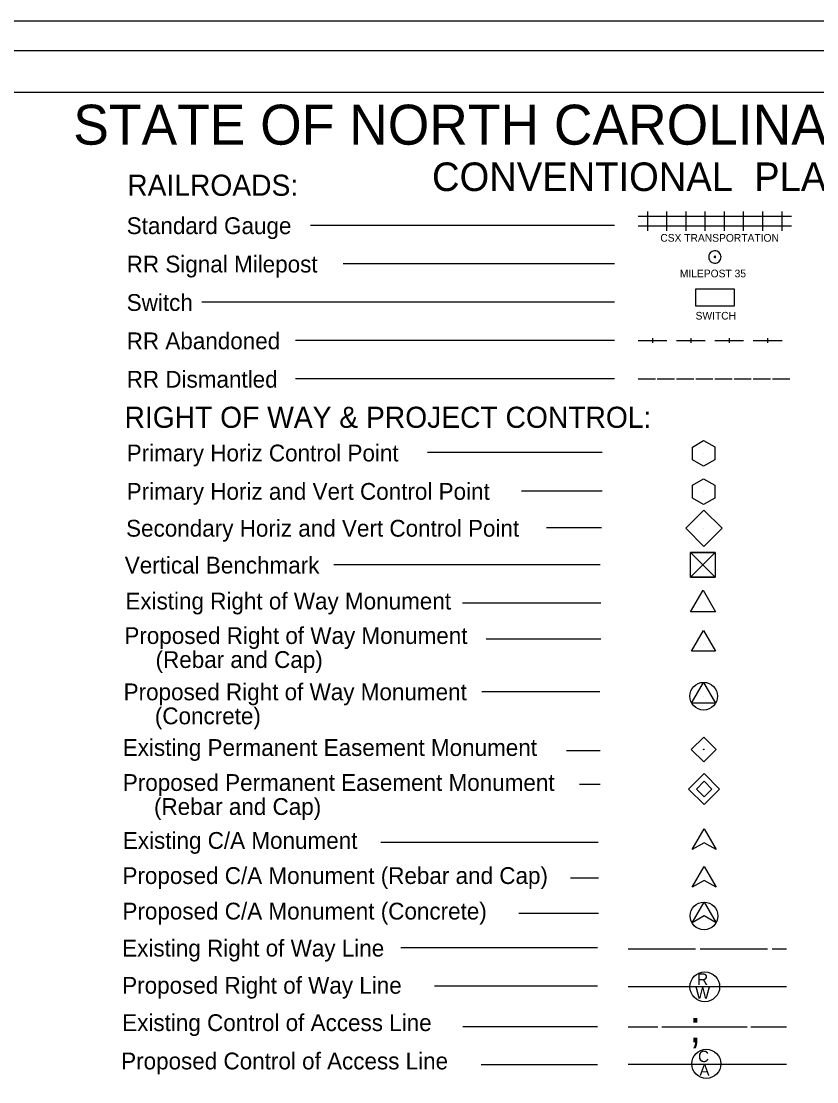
# Model space of a CAD drawing. Extents: x 811508 to 813252, y 647626 to 648754.
# Drawn here: x 811937 to 812366, y 648182 to 648754 of the extents above; entities that cross this region are included whole.
import ezdxf

# ---------------------------------------------------------------- set-up
doc = ezdxf.new("R2010")
doc.units = 0
for name, color, linetype in [('P_RDY_ROW_Permanent_Easement', 7, 'Continuous'), ('Sheet Cutting Line CELL', 7, 'Continuous'), ('Sheet Plot Border Inside CELL', 7, 'Continuous'), ('Sheet Plot Border Outside CELL', 7, 'Continuous'), ('Sheet_Plan', 7, 'Continuous'), ('Sheet_Symbology', 7, 'Continuous'), ('z - Construction', 7, 'Continuous')]:
    doc.layers.add(name, color=color, linetype=linetype)

msp = doc.modelspace()

# ---------------------------------------------------------------- linework, layer by layer
at = {"layer": 'P_RDY_ROW_Permanent_Easement'}
msp.add_line((812305.68, 648339.99), (812305.68, 648339.99), dxfattribs=at)
for points in [[(812305.68, 648348.32), (812314.01, 648339.99), (812305.68, 648331.66), (812297.34, 648339.99)], [(812305.68, 648344.16), (812309.85, 648339.99), (812305.68, 648335.82), (812301.51, 648339.99)]]:
    msp.add_lwpolyline(points, close=True, dxfattribs=at)
at = {"layer": 'Sheet Cutting Line CELL'}
msp.add_line((813217.6, 648737.99), (811533.6, 648737.99), dxfattribs=at)
at = {"layer": 'Sheet Plot Border Inside CELL'}
msp.add_lwpolyline([(811546.6, 647660.44), (813213.1, 647660.44), (813213.1, 648715.54), (811546.6, 648715.54)], close=True, dxfattribs=at)
at = {"layer": 'Sheet Plot Border Outside CELL'}
msp.add_lwpolyline([(811533.6, 647637.99), (813217.6, 647637.99), (813217.6, 648737.99), (811533.6, 648737.99)], close=True, dxfattribs=at)
at = {"layer": 'Sheet_Plan'}
msp.add_line((813213.53, 648715.54), (811546.6, 648715.54), dxfattribs=at)
at = {"layer": 'Sheet_Symbology'}
for p, q in [((812270.08, 648648.82), (812280.43, 648648.82)), ((812275.25, 648641.06), (812275.25, 648651.41)), ((812280.43, 648648.82), (812290.78, 648648.82)), ((812285.6, 648641.06), (812285.6, 648651.41)), ((812290.78, 648648.82), (812301.13, 648648.82)), ((812295.95, 648641.06), (812295.95, 648651.41)), ((812301.13, 648648.82), (812311.48, 648648.82)), ((812306.3, 648641.06), (812306.3, 648651.41)), ((812311.48, 648648.82), (812321.83, 648648.82)), ((812316.65, 648641.06), (812316.65, 648651.41)), ((812321.83, 648648.82), (812332.18, 648648.82)), ((812327, 648641.06), (812327, 648651.41)), ((812332.18, 648648.82), (812342.52, 648648.82)), ((812337.35, 648641.06), (812337.35, 648651.41)), ((812342.52, 648648.82), (812352.87, 648648.82)), ((812347.7, 648641.06), (812347.7, 648651.41)), ((812257.25, 648643.89), (812093.3, 648643.89)), ((812270.08, 648643.65), (812280.43, 648643.65)), ((812280.43, 648643.65), (812290.78, 648643.65)), ((812290.78, 648643.65), (812301.13, 648643.65)), ((812301.13, 648643.65), (812311.48, 648643.65)), ((812311.48, 648643.65), (812321.83, 648643.65)), ((812321.83, 648643.65), (812332.18, 648643.65)), ((812332.18, 648643.65), (812342.52, 648643.65)), ((812342.52, 648643.65), (812352.87, 648643.65)), ((812257.25, 648623.19), (812111.04, 648623.19)), ((812257.25, 648602.49), (812034.82, 648602.49)), ((812257.25, 648581.79), (812085.28, 648581.79)), ((812270.08, 648581.79), (812285.6, 648581.79)), ((812277.84, 648583.09), (812277.84, 648580.5)), ((812290.78, 648581.79), (812306.3, 648581.79)), ((812298.54, 648583.09), (812298.54, 648580.5)), ((812311.48, 648581.79), (812327, 648581.79)), ((812319.24, 648583.09), (812319.24, 648580.5)), ((812332.18, 648581.79), (812347.7, 648581.79)), ((812339.94, 648583.09), (812339.94, 648580.5)), ((812257.25, 648561.09), (812085.28, 648561.09)), ((812257.25, 648561.09), (812085.28, 648561.09)), ((812270.08, 648561.09), (812279.39, 648561.09)), ((812280.43, 648561.09), (812289.74, 648561.09)), ((812290.78, 648561.09), (812300.09, 648561.09)), ((812301.13, 648561.09), (812310.44, 648561.09)), ((812311.48, 648561.09), (812320.79, 648561.09)), ((812321.83, 648561.09), (812331.14, 648561.09)), ((812332.18, 648561.09), (812341.49, 648561.09)), ((812342.52, 648561.09), (812351.84, 648561.09)), ((812250.62, 648521.36), (812156.4, 648521.36)), ((812305.4, 648520.98), (812305.4, 648520.98)), ((812250.62, 648500.66), (812207.23, 648500.66)), ((812305.39, 648500.31), (812305.39, 648500.31)), ((812250.29, 648480.78), (812220.74, 648480.78)), ((812305.53, 648480.57), (812305.53, 648480.57)), ((812249.58, 648460.89), (812105.88, 648460.89)), ((812305.01, 648460.9), (812305.01, 648460.9)), ((812249.9, 648440.21), (812175.33, 648440.21)), ((812250.01, 648420.77), (812188.19, 648420.77)), ((812305.4, 648418.06), (812305.4, 648418.06)), ((812249.49, 648392.41), (812185.85, 648392.41)), ((812305.41, 648390.05), (812305.41, 648390.05)), ((812249.57, 648360.64), (812231.4, 648360.64)), ((812305.49, 648361.32), (812305.49, 648361.32)), ((812249.57, 648342.4), (812238.39, 648342.4)), ((812299.19, 648307.31), (812305.66, 648318.49)), ((812305.66, 648318.49), (812312.13, 648307.31)), ((812248.54, 648311.13), (812131.34, 648311.13)), ((812305.66, 648311.04), (812299.19, 648307.31)), ((812312.13, 648307.31), (812305.66, 648311.04)), ((812299.16, 648287.01), (812305.63, 648298.19)), ((812305.63, 648298.19), (812312.09, 648287.01)), ((812248.64, 648291.95), (812233.57, 648291.95)), ((812305.63, 648290.74), (812299.16, 648287.01)), ((812312.09, 648287.01), (812305.63, 648290.74)), ((812299.16, 648267.86), (812305.63, 648279.04)), ((812305.63, 648279.04), (812312.09, 648267.86)), ((812248.64, 648272.79), (812205.8, 648272.79)), ((812305.63, 648271.58), (812299.16, 648267.86)), ((812312.09, 648267.86), (812305.63, 648271.58)), ((812248.19, 648254.39), (812142.09, 648254.39)), ((812264.78, 648253.8), (812301, 648253.8)), ((812303.59, 648253.8), (812339.82, 648253.8)), ((812342.4, 648253.8), (812350.17, 648253.8)), ((812248.19, 648233.69), (812160.17, 648233.69)), ((812264.78, 648233.56), (812350.17, 648233.56)), ((812248.19, 648211.83), (812175.49, 648211.83)), ((812264.78, 648211.83), (812280.78, 648211.83)), ((812282.85, 648211.83), (812328.82, 648211.83)), ((812330.89, 648211.83), (812350.17, 648211.83)), ((812248.19, 648191.32), (812185.35, 648191.32)), ((812264.78, 648191.71), (812350.17, 648191.71))]:
    msp.add_line(p, q, dxfattribs=at)
for points in [[(812314.85, 648626.88), (812314.78, 648627.55), (812314.58, 648628.22), (812314.24, 648628.83), (812313.78, 648629.3), (812313.24, 648629.7), (812312.63, 648630.04), (812312.03, 648630.17), (812311.29, 648630.24), (812310.62, 648630.1), (812310.01, 648629.9), (812309.41, 648629.56), (812308.93, 648629.1), (812308.53, 648628.49), (812308.26, 648627.88), (812308.13, 648627.21), (812308.13, 648626.54), (812308.26, 648625.87), (812308.53, 648625.26), (812308.93, 648624.66), (812309.41, 648624.19), (812310.01, 648623.85), (812310.62, 648623.65), (812311.29, 648623.51), (812312.03, 648623.58), (812312.63, 648623.72), (812313.24, 648624.05), (812313.78, 648624.45), (812314.24, 648624.93), (812314.58, 648625.53), (812314.78, 648626.2), (812314.85, 648626.88)], [(812311.62, 648627.28), (812311.42, 648627.28), (812311.22, 648627.15), (812311.09, 648626.94), (812311.15, 648626.74), (812311.29, 648626.54), (812311.49, 648626.47), (812311.69, 648626.54), (812311.82, 648626.67), (812311.89, 648626.94), (812311.82, 648627.15), (812311.62, 648627.28)], [(812305.4, 648514.09), (812299.4, 648517.5), (812299.4, 648524.38), (812305.4, 648527.86), (812311.4, 648524.45), (812311.4, 648517.5), (812305.4, 648514.09)], [(812311.71, 648467.6), (812298.29, 648454.18), (812305, 648460.89), (812311.71, 648454.18), (812298.29, 648467.6)], [(812305, 648460.89), (812311.71, 648467.6), (812298.29, 648467.6), (812305, 648460.89)], [(812305, 648460.89), (812298.29, 648454.18), (812311.71, 648454.18), (812305, 648460.89)], [(812298.4, 648435.59), (812305.12, 648447.27), (812311.84, 648435.59), (812298.4, 648435.59)]]:
    msp.add_lwpolyline(points, dxfattribs=at)
for points in [[(812301.13, 648609.7), (812321.83, 648609.7), (812321.83, 648600.28), (812301.13, 648600.28)], [(812299.36, 648503.8), (812305.43, 648507.19), (812311.5, 648503.85), (812311.4, 648496.89), (812305.33, 648493.37), (812299.36, 648496.75)], [(812295.79, 648480.6), (812305.58, 648490.39), (812315.39, 648480.58), (812305.6, 648470.8)], [(812298.29, 648467.6), (812311.71, 648467.6), (812311.71, 648454.18), (812298.29, 648454.18)], [(812298.93, 648414.34), (812305.4, 648425.51), (812311.86, 648414.34)], [(812298.94, 648386.33), (812305.41, 648397.51), (812311.88, 648386.33)], [(812298.77, 648361.32), (812305.49, 648368.04), (812312.22, 648361.32), (812305.49, 648354.6)]]:
    msp.add_lwpolyline(points, close=True, dxfattribs=at)
for centre, radius in [((812305.41, 648390.05), 7.45), ((812305.49, 648361.32), 0.131), ((812305.63, 648271.58), 7.45), ((812306.03, 648233.35), 8.02), ((812306.85, 648191.82), 7.85)]:
    msp.add_circle(centre, radius, dxfattribs=at)
at = {"layer": 'z - Construction'}
msp.add_line((813251.99, 648754), (811508.14, 648754), dxfattribs=at)

# ---------------------------------------------------------------- texts
at = {"layer": 'Sheet_Symbology'}
for s, height, p in [('STATE OF NORTH CAROLINA, DIVISION OF HIGHWAYS', 21.5418, (811965.38, 648687.44)), ('CONVENTIONAL  PLAN SHEET SYMBOLS', 15.387, (812158.9, 648662.45)), ('RAILROADS:', 11.385, (811994.49, 648659.88)), ('Standard Gauge', 9.056, (811994.2, 648639.21)), ('RR Signal Milepost', 9.056, (811994.2, 648618.51)), ('Switch', 9.056, (811994.2, 648597.81)), ('RR Abandoned', 9.056, (811994.2, 648577.11)), ('RR Dismantled', 9.056, (811994.2, 648556.41)), ('RIGHT OF WAY & PROJECT CONTROL:', 11.3847, (811993.03, 648534.75)), ('Primary Horiz Control Point', 9.056, (811994.2, 648516.65)), ('Primary Horiz and Vert Control Point', 9.056, (811994.2, 648495.95)), ('Secondary Horiz and Vert Control Point', 9.056, (811993.88, 648476.07)), ('Vertical Benchmark', 9.056, (811993.17, 648456.18)), ('Existing Right of Way Monument', 9.056, (811993.49, 648436.82)), ('Proposed Right of Way Monument', 9.056, (811992.95, 648418.21)), ('     (Rebar and Cap)', 9.056, (811992.95, 648405.27)), ('Proposed Right of Way Monument', 9.056, (811992.56, 648387.84)), ('     (Concrete)', 9.056, (811992.56, 648374.9)), ('Existing Permanent Easement Monument', 9.056, (811992.06, 648357.83)), ('Proposed Permanent Easement Monument', 9.056, (811992.11, 648338.96)), ('     (Rebar and Cap)', 9.056, (811992.11, 648326.02)), ('Existing C/A Monument', 9.056, (811992.13, 648307.73)), ('Proposed C/A Monument (Rebar and Cap)', 9.056, (811991.91, 648288.79)), ('Proposed C/A Monument (Concrete)', 9.056, (811991.91, 648269.63)), ('Existing Right of Way Line', 9.056, (811991.78, 648249.68)), ('R', 6.29, (812301.82, 648234.29)), ('Proposed Right of Way Line', 9.056, (811991.78, 648229.63)), ('W', 6.29, (812300.92, 648226.89)), ('Existing Control of Access Line', 9.056, (811991.78, 648209.49)), (';', 17.08, (812297.69, 648203.36)), ('Proposed Control of Access Line', 9.056, (811991.21, 648188.81)), ('C', 6.15, (812302.41, 648192.75)), ('A', 6.15, (812303.14, 648185.36))]:
    msp.add_text(s, height=height, dxfattribs=at).set_placement(p)
for s, height, p in [('CSX TRANSPORTATION', 4.1398, (812282.04, 648635.12)), ('MILEPOST 35', 4.1398, (812292.59, 648615.9)), ('SWITCH', 4.14, (812301.07, 648593.13))]:
    msp.add_text(s, height=height, rotation=360, dxfattribs=at).set_placement(p)

doc.saveas('drawing.dxf')
